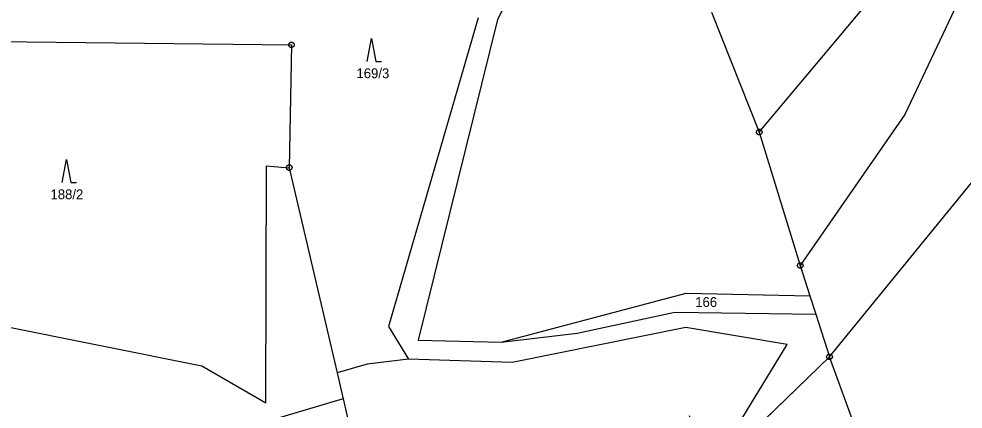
# Model space of a CAD drawing. Extents: x -580551 to -575069, y -1073031 to -1067931.
# Drawn here: x -576922.3 to -576758.6, y -1069818.4 to -1069750.7 of the extents above; entities that cross this region are included whole.
import ezdxf

# ---------------------------------------------------------------- set-up
doc = ezdxf.new("R2010")
doc.units = 0
for name, color, linetype in [('Druh pozemku', 7, 'Continuous'), ('Geodetické body', 7, 'Continuous'), ('Parcela', 7, 'Continuous'), ('Parcelní číslo', 7, 'Continuous'), ('SR - hranice státu', 7, 'Continuous')]:
    doc.layers.add(name, color=color, linetype=linetype)

msp = doc.modelspace()

# ---------------------------------------------------------------- linework, layer by layer
at = {"layer": 'Druh pozemku'}
for points in [[(-576861.96, -1069758.1), (-576861.21, -1069754.1), (-576860.46, -1069758.1), (-576859.46, -1069758.1)], [(-576914.82, -1069779.08), (-576914.07, -1069775.08), (-576913.32, -1069779.08), (-576912.32, -1069779.08)]]:
    msp.add_lwpolyline(points, dxfattribs=at)
at = {"layer": 'Geodetické body'}
for p, q in [((-576875.19, -1069755.25), (-576874.95, -1069755.25)), ((-576794.09, -1069770.35), (-576793.85, -1069770.35)), ((-576875.56, -1069776.53), (-576875.32, -1069776.53)), ((-576786.98, -1069793.52), (-576786.74, -1069793.52)), ((-576781.93, -1069809.35), (-576781.69, -1069809.35))]:
    msp.add_line(p, q, dxfattribs=at)
for points in [[(-576874.92, -1069754.77), (-576874.67, -1069754.95), (-576874.57, -1069755.24), (-576874.67, -1069755.53), (-576874.92, -1069755.71), (-576875.23, -1069755.71), (-576875.48, -1069755.53), (-576875.58, -1069755.24), (-576875.48, -1069754.95), (-576875.23, -1069754.77)], [(-576793.82, -1069769.87), (-576793.57, -1069770.05), (-576793.47, -1069770.34), (-576793.57, -1069770.63), (-576793.82, -1069770.81), (-576794.13, -1069770.81), (-576794.38, -1069770.63), (-576794.48, -1069770.34), (-576794.38, -1069770.05), (-576794.13, -1069769.87)], [(-576875.29, -1069776.05), (-576875.04, -1069776.23), (-576874.94, -1069776.52), (-576875.04, -1069776.81), (-576875.29, -1069776.99), (-576875.6, -1069776.99), (-576875.85, -1069776.81), (-576875.95, -1069776.52), (-576875.85, -1069776.23), (-576875.6, -1069776.05)], [(-576786.71, -1069793.04), (-576786.46, -1069793.22), (-576786.36, -1069793.51), (-576786.46, -1069793.8), (-576786.71, -1069793.98), (-576787.02, -1069793.98), (-576787.27, -1069793.8), (-576787.37, -1069793.51), (-576787.27, -1069793.22), (-576787.02, -1069793.04)], [(-576781.66, -1069808.87), (-576781.41, -1069809.05), (-576781.31, -1069809.34), (-576781.41, -1069809.63), (-576781.66, -1069809.81), (-576781.97, -1069809.81), (-576782.22, -1069809.63), (-576782.32, -1069809.34), (-576782.22, -1069809.05), (-576781.97, -1069808.87)]]:
    msp.add_lwpolyline(points, close=True, dxfattribs=at)
at = {"layer": 'Parcela'}
for p, q in [((-576827.66, -1069728.46), (-576839.37, -1069750.8)), ((-576793.97, -1069770.35), (-576767.38, -1069738.59)), ((-576759.06, -1069746.74), (-576768.77, -1069767.28)), ((-576802.23, -1069749.56), (-576793.97, -1069770.35)), ((-576842.71, -1069750.55), (-576858.25, -1069804.05)), ((-576839.37, -1069750.8), (-576853.13, -1069806.42)), ((-576943.71, -1069754.47), (-576875.07, -1069755.25)), ((-576875.07, -1069755.25), (-576875.44, -1069776.53)), ((-576768.77, -1069767.28), (-576786.86, -1069793.52)), ((-576781.81, -1069809.35), (-576748.86, -1069768.89)), ((-576793.97, -1069770.35), (-576786.86, -1069793.52)), ((-576879.5, -1069817.29), (-576879.38, -1069776.23)), ((-576879.38, -1069776.23), (-576875.44, -1069776.53)), ((-576875.44, -1069776.53), (-576867.16, -1069812.13)), ((-576786.86, -1069793.52), (-576785.19, -1069798.75)), ((-576838.73, -1069806.8), (-576806.64, -1069798.3)), ((-576806.64, -1069798.3), (-576785.19, -1069798.75)), ((-576785.19, -1069798.75), (-576784.18, -1069801.91)), ((-576825.55, -1069805.25), (-576808.62, -1069801.58)), ((-576808.62, -1069801.58), (-576784.18, -1069801.91)), ((-576784.18, -1069801.91), (-576781.81, -1069809.35)), ((-576930.27, -1069802.9), (-576890.62, -1069810.92)), ((-576858.25, -1069804.05), (-576854.79, -1069809.75)), ((-576806.73, -1069804.25), (-576836.8, -1069810.31)), ((-576789.13, -1069807.19), (-576806.73, -1069804.25)), ((-576838.73, -1069806.8), (-576825.55, -1069805.25)), ((-576853.13, -1069806.42), (-576838.73, -1069806.8)), ((-576799.33, -1069823.86), (-576789.13, -1069807.19)), ((-576796.54, -1069823.62), (-576781.81, -1069809.35)), ((-576775.5, -1069826.6), (-576781.81, -1069809.35)), ((-576890.62, -1069810.92), (-576879.5, -1069817.29)), ((-576861.93, -1069810.62), (-576867.16, -1069812.13)), ((-576854.79, -1069809.75), (-576861.93, -1069810.62)), ((-576836.8, -1069810.31), (-576854.79, -1069809.75)), ((-576867.16, -1069812.13), (-576866.12, -1069816.6)), ((-576866.12, -1069816.6), (-576878.33, -1069820.27)), ((-576866.12, -1069816.6), (-576861.52, -1069836.34))]:
    msp.add_line(p, q, dxfattribs=at)
at = {"layer": 'SR - hranice státu'}
msp.add_line((-576781.81, -1069809.35), (-576748.86, -1069768.89), dxfattribs=at)
msp.add_lwpolyline([(-576806.11, -1069819.51), (-576801.19, -1069836.25), (-576798.31, -1069836.768), (-576796.54, -1069823.62), (-576781.81, -1069809.35)], dxfattribs=at)

# ---------------------------------------------------------------- texts
at = {"layer": 'Parcelní číslo'}
for s, p in [('169/3', (-576863.799, -1069761)), ('188/2', (-576916.834, -1069782)), ('166', (-576805.077, -1069800.68))]:
    msp.add_text(s, height=1.7, dxfattribs=at).set_placement(p)

doc.saveas('drawing.dxf')
